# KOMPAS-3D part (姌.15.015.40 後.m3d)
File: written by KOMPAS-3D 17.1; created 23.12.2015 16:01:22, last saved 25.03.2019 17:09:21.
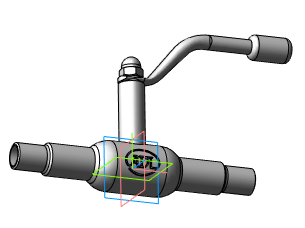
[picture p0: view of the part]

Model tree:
1. Операция без истории:3  (labels: Сталь 20  ГОСТ 1050-88)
